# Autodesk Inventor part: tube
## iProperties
Shininess: 64.0
Length Units: 11269
Angle Units: 11279
Time Units: 11290
Mass Units: 11283
Length Display Precision: 3
Angle Display Precision: 2
Compacted: True
Part Number: tube
Document SubType Name: Modeling
Created: 2005-04
Material: Par défaut
Designer: thchene
Density: 0.0
Volumn: 0.0
Area: 0.0
PropertySet Name: Model Information
Control State: 0
Master: False
Checked Out: False
Author: thchene
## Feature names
1. Extrusion1
2. Extrusion2
